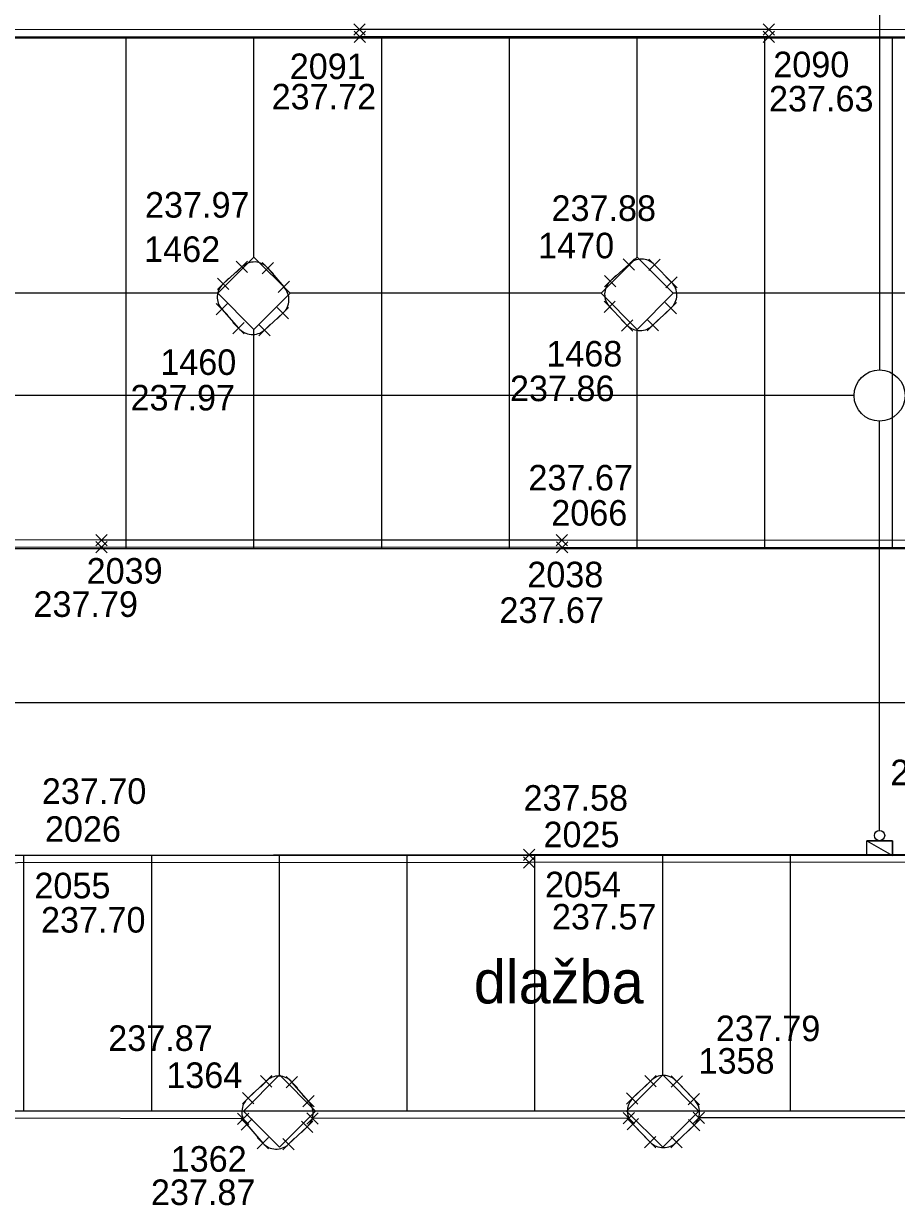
# Model space of a CAD drawing. Extents: x -264165 to -263733, y -1242319 to -1242245.
# Drawn here: x -263887.58 to -263870.5, y -1242299.83 to -1242276.71 of the extents above; entities that cross this region are included whole.
import ezdxf

# ---------------------------------------------------------------- set-up
doc = ezdxf.new("R2010")
doc.units = 0
for name, color, linetype in [('KFA_BOD_CISLO', 7, 'Continuous'), ('KFA_BOD_SYMBOL', 7, 'Continuous'), ('KFA_BOD_VYSKA', 7, 'Continuous'), ('KFA_SO_20-2_OBRUBNIKY_DOLNA_HRANA', 7, 'Continuous'), ('KFA_SO_20-2_OBRUBNIKY_HORNA_HRANA', 7, 'Continuous'), ('KFA_UV_BOD_VYSKA', 7, 'Continuous'), ('POPIS', 7, 'Continuous'), ('PROJEKT_OBRUBNIKY_KOMUNIKACIE', 7, 'Continuous'), ('PROJEKT_TDZ_VODOROVNE', 7, 'Continuous'), ('SITUACIA_DSP_2D', 7, 'Continuous')]:
    doc.layers.add(name, color=color, linetype=linetype)

msp = doc.modelspace()

# ---------------------------------------------------------------- linework, layer by layer
at = {"layer": 'KFA_BOD_SYMBOL'}
for p, q in [((-263881.111, -1242276.928), (-263880.889, -1242276.708)), ((-263880.889, -1242276.928), (-263881.111, -1242276.708)), ((-263873.101, -1242276.933), (-263872.88, -1242276.711)), ((-263872.88, -1242276.933), (-263873.101, -1242276.711)), ((-263881.106, -1242277.075), (-263880.885, -1242276.853)), ((-263880.885, -1242277.075), (-263881.106, -1242276.853)), ((-263873.101, -1242277.076), (-263872.88, -1242276.855)), ((-263872.88, -1242277.076), (-263873.101, -1242276.855)), ((-263875.845, -1242281.529), (-263875.623, -1242281.309)), ((-263875.623, -1242281.529), (-263875.845, -1242281.309)), ((-263875.342, -1242281.535), (-263875.121, -1242281.315)), ((-263875.121, -1242281.535), (-263875.342, -1242281.315)), ((-263883.414, -1242281.576), (-263883.193, -1242281.356)), ((-263883.193, -1242281.576), (-263883.414, -1242281.356)), ((-263882.909, -1242281.6), (-263882.688, -1242281.379)), ((-263882.688, -1242281.6), (-263882.909, -1242281.379)), ((-263883.781, -1242281.906), (-263883.56, -1242281.684)), ((-263883.56, -1242281.906), (-263883.781, -1242281.684)), ((-263882.595, -1242281.967), (-263882.373, -1242281.745)), ((-263882.373, -1242281.967), (-263882.595, -1242281.745)), ((-263876.205, -1242281.856), (-263875.984, -1242281.636)), ((-263875.984, -1242281.856), (-263876.205, -1242281.636)), ((-263875.008, -1242281.877), (-263874.786, -1242281.657)), ((-263874.786, -1242281.877), (-263875.008, -1242281.657)), ((-263883.805, -1242282.404), (-263883.584, -1242282.184)), ((-263883.584, -1242282.404), (-263883.805, -1242282.184)), ((-263882.611, -1242282.484), (-263882.389, -1242282.262)), ((-263882.389, -1242282.484), (-263882.611, -1242282.262)), ((-263876.217, -1242282.359), (-263875.996, -1242282.137)), ((-263875.996, -1242282.359), (-263876.217, -1242282.137)), ((-263875.019, -1242282.382), (-263874.797, -1242282.16)), ((-263874.797, -1242282.382), (-263875.019, -1242282.16)), ((-263875.873, -1242282.72), (-263875.652, -1242282.498)), ((-263875.652, -1242282.72), (-263875.873, -1242282.498)), ((-263875.371, -1242282.715), (-263875.149, -1242282.494)), ((-263875.149, -1242282.715), (-263875.371, -1242282.494)), ((-263883.479, -1242282.772), (-263883.258, -1242282.551)), ((-263883.258, -1242282.772), (-263883.479, -1242282.551)), ((-263882.975, -1242282.812), (-263882.753, -1242282.592)), ((-263882.753, -1242282.812), (-263882.975, -1242282.592)), ((-263886.164, -1242287.062), (-263885.943, -1242286.84)), ((-263885.943, -1242287.062), (-263886.164, -1242286.84)), ((-263886.16, -1242286.921), (-263885.939, -1242286.7)), ((-263885.939, -1242286.921), (-263886.16, -1242286.7)), ((-263877.154, -1242286.923), (-263876.932, -1242286.701)), ((-263876.932, -1242286.923), (-263877.154, -1242286.701)), ((-263877.148, -1242287.062), (-263876.927, -1242286.842)), ((-263876.927, -1242287.062), (-263877.148, -1242286.842)), ((-263877.794, -1242293.082), (-263877.573, -1242292.86)), ((-263877.573, -1242293.082), (-263877.794, -1242292.86)), ((-263877.792, -1242293.227), (-263877.571, -1242293.005)), ((-263877.571, -1242293.227), (-263877.792, -1242293.005)), ((-263882.94, -1242297.511), (-263882.719, -1242297.289)), ((-263882.719, -1242297.511), (-263882.94, -1242297.289)), ((-263875.417, -1242297.507), (-263875.196, -1242297.285)), ((-263875.196, -1242297.507), (-263875.417, -1242297.285)), ((-263874.905, -1242297.512), (-263874.684, -1242297.292)), ((-263874.684, -1242297.512), (-263874.905, -1242297.292)), ((-263882.435, -1242297.528), (-263882.214, -1242297.306)), ((-263882.214, -1242297.528), (-263882.435, -1242297.306)), ((-263883.294, -1242297.84), (-263883.073, -1242297.62)), ((-263883.073, -1242297.84), (-263883.294, -1242297.62)), ((-263882.112, -1242297.896), (-263881.891, -1242297.674)), ((-263881.891, -1242297.896), (-263882.112, -1242297.674)), ((-263875.774, -1242297.847), (-263875.553, -1242297.627)), ((-263875.553, -1242297.847), (-263875.774, -1242297.627)), ((-263874.568, -1242297.863), (-263874.347, -1242297.641)), ((-263874.347, -1242297.863), (-263874.568, -1242297.641)), ((-263883.389, -1242298.245), (-263883.167, -1242298.025)), ((-263883.167, -1242298.245), (-263883.389, -1242298.025)), ((-263883.321, -1242298.355), (-263883.1, -1242298.133)), ((-263883.1, -1242298.355), (-263883.321, -1242298.133)), ((-263882.138, -1242298.403), (-263881.916, -1242298.181)), ((-263881.916, -1242298.403), (-263882.138, -1242298.181)), ((-263882.033, -1242298.235), (-263881.812, -1242298.015)), ((-263881.812, -1242298.235), (-263882.033, -1242298.015)), ((-263875.845, -1242298.231), (-263875.623, -1242298.011)), ((-263875.623, -1242298.231), (-263875.845, -1242298.011)), ((-263875.763, -1242298.352), (-263875.541, -1242298.13)), ((-263875.541, -1242298.352), (-263875.763, -1242298.13)), ((-263874.562, -1242298.369), (-263874.341, -1242298.147)), ((-263874.341, -1242298.369), (-263874.562, -1242298.147)), ((-263874.474, -1242298.227), (-263874.253, -1242298.005)), ((-263874.253, -1242298.227), (-263874.474, -1242298.005)), ((-263883.003, -1242298.718), (-263882.781, -1242298.498)), ((-263882.781, -1242298.718), (-263883.003, -1242298.498)), ((-263882.502, -1242298.741), (-263882.28, -1242298.519)), ((-263882.28, -1242298.741), (-263882.502, -1242298.519)), ((-263875.422, -1242298.698), (-263875.201, -1242298.478)), ((-263875.201, -1242298.698), (-263875.422, -1242298.478)), ((-263874.908, -1242298.698), (-263874.687, -1242298.477)), ((-263874.687, -1242298.698), (-263874.908, -1242298.477))]:
    msp.add_line(p, q, dxfattribs=at)
at = {"layer": 'KFA_SO_20-2_OBRUBNIKY_DOLNA_HRANA'}
for points in [[(-263816.727, -1242276.824), (-263824.896, -1242276.832), (-263841.932, -1242276.838), (-263860.969, -1242276.825), (-263872.991, -1242276.822), (-263881, -1242276.818), (-263897.019, -1242276.831), (-263905.035, -1242276.846), (-263913.057, -1242276.848), (-263917.557, -1242276.899)], [(-263817.074, -1242276.98), (-263824.904, -1242276.976), (-263831.918, -1242276.976), (-263841.931, -1242276.979), (-263850.949, -1242276.976), (-263860.958, -1242276.969), (-263872.991, -1242276.965), (-263880.996, -1242276.964), (-263889.006, -1242276.968), (-263897.017, -1242276.976), (-263905.035, -1242276.99), (-263913.048, -1242276.994), (-263917.092, -1242277.009)], [(-263819.103, -1242286.786), (-263819.439, -1242286.959), (-263828.996, -1242286.962), (-263838.005, -1242286.965), (-263845.009, -1242286.967), (-263853.017, -1242286.968), (-263861.032, -1242286.966), (-263868.037, -1242286.96), (-263877.037, -1242286.952), (-263886.053, -1242286.951), (-263895.068, -1242286.953), (-263904.067, -1242286.955), (-263910.084, -1242286.961), (-263917.346, -1242286.958)], [(-263819.419, -1242286.819), (-263828.995, -1242286.822), (-263838.007, -1242286.821), (-263845.022, -1242286.826), (-263853.012, -1242286.818), (-263861.03, -1242286.825), (-263868.034, -1242286.816), (-263877.043, -1242286.812), (-263886.05, -1242286.81), (-263895.064, -1242286.807), (-263904.07, -1242286.816), (-263910.08, -1242286.821), (-263917.062, -1242286.824)], [(-263817.492, -1242292.982), (-263829.632, -1242292.973), (-263839.651, -1242292.963), (-263849.653, -1242292.97), (-263858.67, -1242292.978), (-263866.671, -1242292.969), (-263877.683, -1242292.971), (-263887.693, -1242292.984), (-263898.705, -1242293.002), (-263909.705, -1242293.003), (-263917.41, -1242292.997)], [(-263817.431, -1242293.129), (-263829.63, -1242293.121), (-263839.649, -1242293.107), (-263849.656, -1242293.117), (-263858.667, -1242293.124), (-263866.668, -1242293.115), (-263877.682, -1242293.116), (-263887.695, -1242293.128), (-263898.705, -1242293.142), (-263909.706, -1242293.151), (-263917.057, -1242293.143)]]:
    msp.add_lwpolyline(points, dxfattribs=at)
at = {"layer": 'KFA_SO_20-2_OBRUBNIKY_HORNA_HRANA'}
for p, q in [((-263883.671, -1242281.795), (-263883.303, -1242281.466)), ((-263882.798, -1242281.489), (-263882.484, -1242281.856)), ((-263876.095, -1242281.746), (-263875.734, -1242281.419)), ((-263875.231, -1242281.425), (-263874.897, -1242281.767)), ((-263876.106, -1242282.248), (-263875.763, -1242282.609)), ((-263874.908, -1242282.271), (-263875.26, -1242282.604)), ((-263883.694, -1242282.294), (-263883.368, -1242282.661)), ((-263882.5, -1242282.373), (-263882.864, -1242282.702)), ((-263882.829, -1242297.4), (-263883.183, -1242297.73)), ((-263882.002, -1242297.785), (-263882.324, -1242297.417)), ((-263875.664, -1242297.737), (-263875.307, -1242297.396)), ((-263874.795, -1242297.402), (-263874.458, -1242297.752)), ((-263883.278, -1242298.135), (-263889.325, -1242298.119)), ((-263875.734, -1242298.121), (-263881.922, -1242298.125)), ((-263868.255, -1242298.118), (-263874.363, -1242298.116)), ((-263883.21, -1242298.244), (-263882.892, -1242298.608)), ((-263882.391, -1242298.63), (-263882.027, -1242298.292)), ((-263875.312, -1242298.588), (-263875.652, -1242298.241)), ((-263874.797, -1242298.587), (-263874.452, -1242298.258))]:
    msp.add_line(p, q, dxfattribs=at)
for centre, major_axis, ratio, start_param, end_param in [((-263875.485, -1242281.654), (-0.335, -0.071), 0.999339, 3.666159, 5.317438), ((-263883.061, -1242281.718), (-0.349, -0.014), 0.999726, 3.817259, 5.438361), ((-263883.436, -1242282.056), (0.154, -0.315), 0.999575, 3.419425, 5.002674), ((-263875.85, -1242282.002), (-0.215, -0.283), 0.99853, 4.554045, 6.126907), ((-263875.132, -1242282.014), (-0.246, 0.236), 0.999822, 3.053112, 4.718361), ((-263882.744, -1242282.107), (0.149, 0.329), 0.999382, 4.309539, 5.905305), ((-263883.096, -1242282.436), (0.215, -0.28), 0.998973, 4.749049, 6.346968), ((-263875.514, -1242282.356), (0.354, -0.018), 0.999439, 3.983891, 5.559673), ((-263882.584, -1242297.637), (-0.341, 0.011), 0.99964, 3.878149, 5.546629), ((-263875.054, -1242297.635), (-0.347, 0.034), 0.999749, 3.974685, 5.624644), ((-263882.944, -1242298), (-0.098, -0.348), 0.999649, 4.140893, 5.727283), ((-263875.401, -1242297.983), (0.137, -0.333), 0.999985, 3.56897, 5.12029), ((-263874.693, -1242298.008), (0.142, 0.317), 0.999901, 4.331022, 5.961844), ((-263882.263, -1242298.026), (-0.026, 0.355), 0.996702, 3.797246, 5.384184), ((-263882.631, -1242298.378), (0.337, -0.086), 0.99981, 4.112809, 5.723997), ((-263875.055, -1242298.337), (0.354, 0.064), 0.999446, 3.737774, 5.335124)]:
    msp.add_ellipse(centre, major_axis=major_axis, ratio=ratio, start_param=start_param, end_param=end_param, dxfattribs=at)
at = {"layer": 'PROJEKT_OBRUBNIKY_KOMUNIKACIE'}
for p, q in [((-263917.08, -1242276.982), (-263817.068, -1242276.982)), ((-263819.568, -1242286.982), (-263917.08, -1242286.982)), ((-263817.19, -1242292.982), (-263917.08, -1242292.982)), ((-263815.601, -1242297.982), (-263917.08, -1242297.982))]:
    msp.add_line(p, q, dxfattribs=at)
for points in [[(-263883.068, -1242281.275), (-263882.361, -1242281.982), (-263883.068, -1242282.689), (-263883.775, -1242281.982), (-263883.068, -1242281.275)], [(-263875.568, -1242281.275), (-263874.861, -1242281.982), (-263875.568, -1242282.689), (-263876.275, -1242281.982), (-263875.568, -1242281.275)], [(-263882.568, -1242297.275), (-263881.861, -1242297.982), (-263882.568, -1242298.689), (-263883.275, -1242297.982), (-263882.568, -1242297.275)], [(-263875.068, -1242297.275), (-263874.361, -1242297.982), (-263875.068, -1242298.689), (-263875.775, -1242297.982), (-263875.068, -1242297.275)]]:
    msp.add_lwpolyline(points, dxfattribs=at)
at = {"layer": 'PROJEKT_TDZ_VODOROVNE'}
for p, q in [((-263885.568, -1242281.982), (-263885.568, -1242276.982)), ((-263883.068, -1242281.275), (-263883.068, -1242276.982)), ((-263880.568, -1242281.982), (-263880.568, -1242276.982)), ((-263878.068, -1242281.982), (-263878.068, -1242276.982)), ((-263875.568, -1242281.275), (-263875.568, -1242276.982)), ((-263873.068, -1242281.982), (-263873.068, -1242276.982)), ((-263870.568, -1242281.982), (-263870.568, -1242276.982)), ((-263883.775, -1242281.982), (-263889.861, -1242281.982)), ((-263885.568, -1242286.982), (-263885.568, -1242281.982)), ((-263876.275, -1242281.982), (-263882.361, -1242281.982)), ((-263880.568, -1242286.982), (-263880.568, -1242281.982)), ((-263878.068, -1242286.982), (-263878.068, -1242281.982)), ((-263868.775, -1242281.982), (-263874.861, -1242281.982)), ((-263873.068, -1242286.982), (-263873.068, -1242281.982)), ((-263870.568, -1242286.982), (-263870.568, -1242281.982)), ((-263883.068, -1242286.982), (-263883.068, -1242282.689)), ((-263875.568, -1242286.982), (-263875.568, -1242282.689)), ((-263819.531, -1242289.994), (-263917.477, -1242289.994)), ((-263887.568, -1242297.982), (-263887.568, -1242292.982)), ((-263885.068, -1242297.982), (-263885.068, -1242292.982)), ((-263882.568, -1242297.275), (-263882.568, -1242292.982)), ((-263880.068, -1242297.982), (-263880.068, -1242292.982)), ((-263877.568, -1242297.982), (-263877.568, -1242292.982)), ((-263875.068, -1242297.275), (-263875.068, -1242292.982)), ((-263872.568, -1242297.982), (-263872.568, -1242292.982))]:
    msp.add_line(p, q, dxfattribs=at)
at = {"layer": 'SITUACIA_DSP_2D'}
for p, q in [((-263870.824, -1242271.473), (-263870.824, -1242283.482)), ((-263871.324, -1242283.982), (-263903.413, -1242283.982)), ((-263870.824, -1242292.492), (-263870.824, -1242284.482)), ((-263871.074, -1242292.693), (-263870.574, -1242292.693)), ((-263871.074, -1242292.983), (-263871.074, -1242292.693)), ((-263871.074, -1242292.693), (-263870.574, -1242292.983)), ((-263871.074, -1242292.693), (-263870.574, -1242292.983)), ((-263870.574, -1242292.693), (-263871.074, -1242292.693)), ((-263870.574, -1242292.693), (-263870.574, -1242292.983)), ((-263870.574, -1242292.983), (-263870.574, -1242292.693)), ((-263870.574, -1242292.983), (-263871.074, -1242292.983)), ((-263815.601, -1242297.982), (-263917.08, -1242297.982))]:
    msp.add_line(p, q, dxfattribs=at)
for points in [[(-263883.068, -1242281.275), (-263882.361, -1242281.982), (-263883.068, -1242282.689), (-263883.775, -1242281.982)], [(-263875.568, -1242281.275), (-263874.861, -1242281.982), (-263875.568, -1242282.689), (-263876.275, -1242281.982)], [(-263882.568, -1242297.275), (-263881.861, -1242297.982), (-263882.568, -1242298.689), (-263883.275, -1242297.982)], [(-263875.068, -1242297.275), (-263874.361, -1242297.982), (-263875.068, -1242298.689), (-263875.775, -1242297.982)]]:
    msp.add_lwpolyline(points, close=True, dxfattribs=at)
for centre, radius in [((-263870.824, -1242283.982), 0.5), ((-263870.824, -1242292.592), 0.1)]:
    msp.add_circle(centre, radius, dxfattribs=at)

# ---------------------------------------------------------------- texts
at = {"layer": 'KFA_BOD_CISLO'}
for s, p in [('2091', (-263882.367, -1242277.79)), ('2090', (-263872.904, -1242277.754)), ('1462', (-263885.217, -1242281.368)), ('1470', (-263877.506, -1242281.297)), ('1468', (-263877.346, -1242283.414)), ('1460', (-263884.901, -1242283.579)), ('2066', (-263877.249, -1242286.527)), ('2039', (-263886.342, -1242287.662)), ('2038', (-263877.718, -1242287.734)), ('2026', (-263887.158, -1242292.714)), ('2025', (-263877.401, -1242292.82)), ('2055', (-263887.364, -1242293.819)), ('2054', (-263877.371, -1242293.799)), ('1358', (-263874.367, -1242297.249)), ('1364', (-263884.783, -1242297.53)), ('1362', (-263884.697, -1242299.168))]:
    msp.add_text(s, height=0.5, dxfattribs=at).set_placement(p)
at = {"layer": 'KFA_BOD_VYSKA'}
for s, p in [('237.72', (-263882.721, -1242278.384)), ('237.63', (-263872.988, -1242278.424)), ('237.97', (-263885.199, -1242280.501)), ('237.88', (-263877.244, -1242280.566)), ('237.86', (-263878.057, -1242284.092)), ('237.97', (-263885.483, -1242284.274)), ('237.67', (-263877.696, -1242285.839)), ('237.79', (-263887.383, -1242288.313)), ('237.67', (-263878.264, -1242288.431)), ('237.70', (-263887.219, -1242291.972)), ('237.58', (-263877.792, -1242292.105)), ('237.70', (-263887.235, -1242294.49)), ('237.57', (-263877.236, -1242294.429)), ('237.79', (-263874.029, -1242296.614)), ('237.87', (-263885.919, -1242296.805)), ('237.87', (-263885.084, -1242299.82))]:
    msp.add_text(s, height=0.5, dxfattribs=at).set_placement(p)
at = {"layer": 'KFA_UV_BOD_VYSKA'}
msp.add_text('237.49', height=0.5, dxfattribs=at).set_placement((-263870.612, -1242291.606))
at = {"layer": 'POPIS'}
msp.add_text('dlažba', height=0.8438, dxfattribs=at).set_placement((-263878.765, -1242295.876))

doc.saveas('drawing.dxf')
